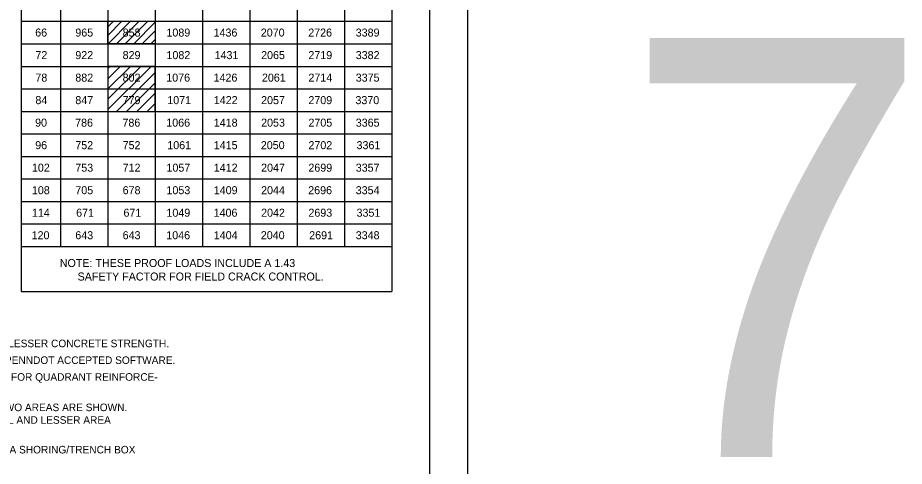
# Model space of a CAD drawing. Extents: x -22562 to -18409, y 3991 to 7171.
# Drawn here: x -19722.1 to -19370.7, y 4225.4 to 4403.1 of the extents above; entities that cross this region are included whole.
import ezdxf

# ---------------------------------------------------------------- set-up
doc = ezdxf.new("R2010")
doc.units = 0
for name, color, linetype in [('1', 7, 'Continuous'), ('2', 7, 'Continuous'), ('3', 7, 'Continuous'), ('4', 7, 'Continuous'), ('PLT-BNDY', 7, 'Continuous')]:
    doc.layers.add(name, color=color, linetype=linetype)

msp = doc.modelspace()

# ---------------------------------------------------------------- linework, layer by layer
at = {"layer": '1'}
for p, q in [((-19720.77, 4401.64), (-19720.77, 4401.64)), ((-19686.36, 4401.64), (-19686.36, 4401.64)), ((-19686.36, 4399.47), (-19684.19, 4401.64)), ((-19686.36, 4396.07), (-19680.79, 4401.64)), ((-19686.31, 4392.72), (-19677.39, 4401.64)), ((-19682.91, 4392.72), (-19673.99, 4401.64)), ((-19679.51, 4392.72), (-19670.59, 4401.64)), ((-19676.12, 4392.72), (-19667.6, 4401.24)), ((-19667.6, 4401.64), (-19667.6, 4401.64)), ((-19712.95, 4397.18), (-19712.95, 4397.18)), ((-19695.74, 4397.18), (-19695.74, 4397.18)), ((-19676.98, 4397.18), (-19676.98, 4397.18)), ((-19672.72, 4392.72), (-19667.6, 4397.84)), ((-19639.47, 4397.18), (-19639.47, 4397.18)), ((-19620.72, 4397.18), (-19620.72, 4397.18)), ((-19601.96, 4397.18), (-19601.96, 4397.18)), ((-19583.2, 4397.18), (-19583.2, 4397.18)), ((-19669.32, 4392.72), (-19667.6, 4394.44)), ((-19720.77, 4392.72), (-19720.77, 4392.72)), ((-19686.36, 4392.72), (-19686.36, 4392.72)), ((-19667.6, 4392.72), (-19667.6, 4392.72)), ((-19712.95, 4388.26), (-19712.95, 4388.26)), ((-19695.74, 4388.26), (-19695.74, 4388.26)), ((-19676.98, 4388.26), (-19676.98, 4388.26)), ((-19639.47, 4388.26), (-19639.47, 4388.26)), ((-19620.72, 4388.26), (-19620.72, 4388.26)), ((-19601.96, 4388.26), (-19601.96, 4388.26)), ((-19583.2, 4388.26), (-19583.2, 4388.26)), ((-19720.77, 4383.8), (-19720.77, 4383.8)), ((-19686.36, 4383.8), (-19686.36, 4383.8)), ((-19686.36, 4383), (-19685.56, 4383.8)), ((-19686.36, 4378.92), (-19681.48, 4383.8)), ((-19686.36, 4374.84), (-19677.4, 4383.8)), ((-19686.36, 4370.77), (-19673.33, 4383.8)), ((-19686.36, 4366.69), (-19669.25, 4383.8)), ((-19667.6, 4383.8), (-19667.6, 4383.8)), ((-19712.95, 4379.34), (-19712.95, 4379.34)), ((-19695.74, 4379.34), (-19695.74, 4379.34)), ((-19683.01, 4365.96), (-19667.6, 4381.37)), ((-19676.98, 4379.34), (-19676.98, 4379.34)), ((-19639.47, 4379.34), (-19639.47, 4379.34)), ((-19620.72, 4379.34), (-19620.72, 4379.34)), ((-19601.96, 4379.34), (-19601.96, 4379.34)), ((-19583.2, 4379.34), (-19583.2, 4379.34)), ((-19678.93, 4365.96), (-19667.6, 4377.29)), ((-19720.77, 4374.88), (-19720.77, 4374.88)), ((-19674.86, 4365.96), (-19667.6, 4373.21)), ((-19712.95, 4370.42), (-19712.95, 4370.42)), ((-19695.74, 4370.42), (-19695.74, 4370.42)), ((-19676.98, 4370.42), (-19676.98, 4370.42)), ((-19670.78, 4365.96), (-19667.6, 4369.14)), ((-19639.47, 4370.42), (-19639.47, 4370.42)), ((-19620.72, 4370.42), (-19620.72, 4370.42)), ((-19601.96, 4370.42), (-19601.96, 4370.42)), ((-19583.2, 4370.42), (-19583.2, 4370.42)), ((-19720.77, 4365.96), (-19720.77, 4365.96)), ((-19686.36, 4365.96), (-19686.36, 4365.96)), ((-19667.6, 4365.96), (-19667.6, 4365.96)), ((-19712.95, 4361.5), (-19712.95, 4361.5)), ((-19695.74, 4361.5), (-19695.74, 4361.5)), ((-19676.98, 4361.5), (-19676.98, 4361.5)), ((-19639.47, 4361.5), (-19639.47, 4361.5)), ((-19620.72, 4361.5), (-19620.72, 4361.5)), ((-19601.96, 4361.5), (-19601.96, 4361.5)), ((-19583.2, 4361.5), (-19583.2, 4361.5)), ((-19720.77, 4357.04), (-19720.77, 4357.04)), ((-19712.95, 4352.58), (-19712.95, 4352.58)), ((-19695.74, 4352.58), (-19695.74, 4352.58)), ((-19676.98, 4352.58), (-19676.98, 4352.58)), ((-19639.47, 4352.58), (-19639.47, 4352.58)), ((-19620.72, 4352.58), (-19620.72, 4352.58)), ((-19601.96, 4352.58), (-19601.96, 4352.58)), ((-19583.2, 4352.58), (-19583.2, 4352.58)), ((-19720.77, 4348.12), (-19720.77, 4348.12)), ((-19712.95, 4343.66), (-19712.95, 4343.66)), ((-19695.74, 4343.66), (-19695.74, 4343.66)), ((-19676.98, 4343.66), (-19676.98, 4343.66)), ((-19639.47, 4343.66), (-19639.47, 4343.66)), ((-19620.72, 4343.66), (-19620.72, 4343.66)), ((-19601.96, 4343.66), (-19601.96, 4343.66)), ((-19583.2, 4343.66), (-19583.2, 4343.66)), ((-19720.77, 4339.2), (-19720.77, 4339.2)), ((-19712.95, 4334.74), (-19712.95, 4334.74)), ((-19695.74, 4334.74), (-19695.74, 4334.74)), ((-19676.98, 4334.74), (-19676.98, 4334.74)), ((-19639.47, 4334.74), (-19639.47, 4334.74)), ((-19620.72, 4334.74), (-19620.72, 4334.74)), ((-19601.96, 4334.74), (-19601.96, 4334.74)), ((-19583.2, 4334.74), (-19583.2, 4334.74)), ((-19720.77, 4330.28), (-19720.77, 4330.28)), ((-19712.95, 4325.82), (-19712.95, 4325.82)), ((-19695.74, 4325.82), (-19695.74, 4325.82)), ((-19639.47, 4325.82), (-19639.47, 4325.82)), ((-19620.72, 4325.82), (-19620.72, 4325.82)), ((-19601.96, 4325.82), (-19601.96, 4325.82)), ((-19583.2, 4325.82), (-19583.2, 4325.82)), ((-19720.77, 4321.36), (-19720.77, 4321.36)), ((-19712.95, 4316.9), (-19712.95, 4316.9)), ((-19695.74, 4316.9), (-19695.74, 4316.9)), ((-19639.47, 4316.9), (-19639.47, 4316.9)), ((-19620.72, 4316.9), (-19620.72, 4316.9)), ((-19601.96, 4316.9), (-19601.96, 4316.9)), ((-19583.2, 4316.9), (-19583.2, 4316.9)), ((-19720.77, 4312.44), (-19720.77, 4312.44))]:
    msp.add_line(p, q, dxfattribs=at)
for points in [[(-19686.36, 4392.72), (-19686.36, 4401.64), (-19667.6, 4401.64), (-19667.6, 4392.72), (-19686.36, 4392.72)], [(-19686.36, 4365.96), (-19667.6, 4365.96), (-19667.6, 4383.8), (-19686.36, 4383.8), (-19686.36, 4365.96)]]:
    msp.add_lwpolyline(points, dxfattribs=at)
at = {"layer": '2'}
for p, q in [((-19558.85, 4570.37), (-19558.85, 4006.37)), ((-19720.77, 4561.14), (-19720.77, 4294.6)), ((-19573.81, 4561.14), (-19573.81, 4294.6)), ((-19705.12, 4538.19), (-19705.12, 4312.44)), ((-19686.36, 4538.19), (-19686.36, 4312.44)), ((-19667.6, 4538.19), (-19667.6, 4312.44)), ((-19648.85, 4538.19), (-19648.85, 4312.44)), ((-19630.09, 4538.19), (-19630.09, 4312.44)), ((-19611.33, 4538.19), (-19611.33, 4312.44)), ((-19592.57, 4538.19), (-19592.57, 4312.44)), ((-19720.77, 4401.64), (-19573.81, 4401.64)), ((-19720.77, 4392.72), (-19573.81, 4392.72)), ((-19720.77, 4383.8), (-19573.81, 4383.8)), ((-19720.77, 4374.88), (-19573.81, 4374.88)), ((-19720.77, 4365.96), (-19573.81, 4365.96)), ((-19720.77, 4357.04), (-19573.81, 4357.04)), ((-19720.77, 4348.12), (-19573.81, 4348.12)), ((-19720.77, 4339.2), (-19573.81, 4339.2)), ((-19720.77, 4330.28), (-19573.81, 4330.28)), ((-19720.77, 4321.36), (-19573.81, 4321.36)), ((-19720.77, 4312.44), (-19573.81, 4312.44)), ((-19720.77, 4294.6), (-19573.81, 4294.6))]:
    msp.add_line(p, q, dxfattribs=at)
at = {"layer": 'PLT-BNDY'}
msp.add_lwpolyline([(-20384.85, 4585.37), (-19543.85, 4585.37), (-19543.85, 3991.37), (-20384.85, 3991.37)], close=True, dxfattribs=at)

# ---------------------------------------------------------------- texts
at = {"layer": '1'}
for s, height, p in [('66', 3.172, (-19715.18, 4395.6)), ('965', 3.172, (-19699.28, 4395.6)), ('858', 3.172, (-19680.52, 4395.6)), ('1436', 3.172, (-19644.47, 4395.6)), ('2070', 3.172, (-19625.75, 4395.6)), ('2726', 3.172, (-19606.95, 4395.6)), ('3389', 3.172, (-19588.13, 4395.6)), ('72', 3.172, (-19715.11, 4386.67)), ('922', 3.172, (-19699.28, 4386.67)), ('829', 3.172, (-19680.53, 4386.67)), ('1431', 3.172, (-19644.07, 4386.67)), ('2065', 3.172, (-19625.63, 4386.67)), ('2719', 3.172, (-19606.89, 4386.67)), ('3382', 3.172, (-19588.12, 4386.67)), ('78', 3.172, (-19715.11, 4377.75)), ('882', 3.172, (-19699.28, 4377.75)), ('802', 3.172, (-19680.53, 4377.75)), ('1426', 3.172, (-19644.47, 4377.75)), ('2061', 3.172, (-19625.31, 4377.75)), ('2714', 3.172, (-19606.87, 4377.75)), ('3375', 3.172, (-19588.12, 4377.75)), ('84', 3.172, (-19715.11, 4368.83)), ('847', 3.172, (-19699.28, 4368.83)), ('779', 3.172, (-19680.53, 4368.83)), ('1422', 3.172, (-19644.39, 4368.83)), ('2057', 3.172, (-19625.63, 4368.83)), ('2709', 3.172, (-19606.89, 4368.83)), ('3370', 3.172, (-19588.24, 4368.83)), ('90', 3.172, (-19715.23, 4359.91)), ('786', 3.172, (-19699.36, 4359.91)), ('786', 3.172, (-19680.6, 4359.91)), ('1418', 3.172, (-19644.39, 4359.91)), ('2053', 3.172, (-19625.63, 4359.91)), ('2705', 3.172, (-19606.87, 4359.91)), ('3365', 3.172, (-19588.12, 4359.91)), ('96', 3.172, (-19715.18, 4350.99)), ('752', 3.172, (-19699.28, 4350.99)), ('752', 3.172, (-19680.53, 4350.99)), ('1415', 3.172, (-19644.39, 4350.99)), ('2050', 3.172, (-19625.75, 4350.99)), ('2702', 3.172, (-19606.87, 4350.99)), ('3361', 3.172, (-19587.8, 4350.99)), ('102', 3.172, (-19716.49, 4342.07)), ('753', 3.172, (-19699.28, 4342.07)), ('712', 3.172, (-19680.52, 4342.07)), ('1412', 3.172, (-19644.39, 4342.07)), ('2047', 3.172, (-19625.63, 4342.07)), ('2699', 3.172, (-19606.89, 4342.07)), ('3357', 3.172, (-19588.12, 4342.07)), ('108', 3.172, (-19716.49, 4333.15)), ('705', 3.172, (-19699.28, 4333.15)), ('678', 3.172, (-19680.52, 4333.15)), ('1409', 3.172, (-19644.4, 4333.15)), ('2044', 3.172, (-19625.63, 4333.15)), ('2696', 3.172, (-19606.95, 4333.15)), ('3354', 3.172, (-19588.12, 4333.15)), ('114', 3.172, (-19716.49, 4324.23)), ('671', 3.172, (-19698.96, 4324.23)), ('671', 3.172, (-19680.2, 4324.23)), ('1406', 3.172, (-19644.46, 4324.23)), ('2042', 3.172, (-19625.63, 4324.23)), ('2693', 3.172, (-19606.88, 4324.23)), ('3351', 3.172, (-19587.8, 4324.23)), ('120', 3.172, (-19716.61, 4315.31)), ('643', 3.172, (-19699.28, 4315.31)), ('643', 3.172, (-19680.52, 4315.31)), ('1404', 3.172, (-19644.39, 4315.31)), ('2040', 3.172, (-19625.75, 4315.31)), ('2691', 3.172, (-19606.56, 4315.31)), ('3348', 3.172, (-19588.12, 4315.31)), ('NOTE: THESE PROOF LOADS INCLUDE A 1.43', 3.1718, (-19705.45, 4304.3)), ('      SAFETY FACTOR FOR FIELD CRACK CONTROL.', 3.1718, (-19705.45, 4298.95)), ('5) FOR PIPE DIAMETERS GREATER THAN 48", USE TYPE A SHORING/TRENCH BOX', 3, (-19836.03, 4230.45))]:
    msp.add_text(s, height=height, dxfattribs=at).set_placement(p)
at = {"layer": '2'}
msp.add_text('7', height=166.03, dxfattribs=at).set_placement((-19482.98, 4229.03))
at = {"layer": '3'}
for s, p in [('1089', (-19663.16, 4395.6)), ('1082', (-19663.15, 4386.67)), ('1076', (-19663.22, 4377.75)), ('1071', (-19662.83, 4368.83)), ('1066', (-19663.22, 4359.91)), ('1061', (-19662.83, 4350.99)), ('1057', (-19663.15, 4342.07)), ('1053', (-19663.15, 4333.15)), ('1049', (-19663.16, 4324.23)), ('1046', (-19663.22, 4315.31))]:
    msp.add_text(s, height=3.172, dxfattribs=at).set_placement(p)
at = {"layer": '4'}
for s, p in [('1) * INDICATES SAME STEEL AREA AS SHOWN FOR THE LESSER CONCRETE STRENGTH.', (-19835.75, 4272.53)), ('2) ** INDICATES A SPECIAL DESIGN IS REQUIRED.  USE PENNDOT ACCEPTED SOFTWARE.', (-19835.75, 4265.9)), ('3) ELLIPTICAL REINFORCING IS NOT ALLOWED, EXCEPT FOR QUADRANT REINFORCE-', (-19835.57, 4259.25)), ('4) FOR DOUBLE CIRCULAR STEEL REINFORCED PIPE, TWO AREAS ARE SHOWN.', (-19836.05, 4247.2)), ('THE GREATER AREA IS FOR THE INNER CAGE STEEL AND LESSER AREA', (-19827.86, 4242.2))]:
    msp.add_text(s, height=3, dxfattribs=at).set_placement(p)

doc.saveas('drawing.dxf')
